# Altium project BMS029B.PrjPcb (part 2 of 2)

## Sheet BMS029B_FETs.SchDoc: FETs
size 431 x 279 mm; Date: Not shown in title block; ApprovedBy: Not shown in title block; CheckedBy: Not shown in title block; Author: Not shown in title block; CompanyName: Not shown in title block; DrawnBy: M Sunna; Engineer: Not shown in title block; Organization: Not shown in title block; Address1: Not shown in title block; Address2: Not shown in title block; Address3: Not shown in title block; Address4: Not shown in title block; DocumentNumber: 3; Revision: Use project parameter SCH_Rev; SheetNumber: 3; SheetTotal: 5; PageSetup: Record=PageOptions¦CenterHorizontal=True¦CenterVertical=True¦PrintScale=1.00¦XCorrection=1.00¦YCorrection=1.00¦PrintKind=0¦BorderSize=5000000¦LeftOffset=0¦BottomOffset=0¦Orientation=2¦PaperLength=1000¦PaperWidth=1000¦Scale=100¦PaperSource=15¦PrintQuality=600¦MediaType=1¦DitherType=10¦PaperKind=Letter¦PrintScaleMode=1
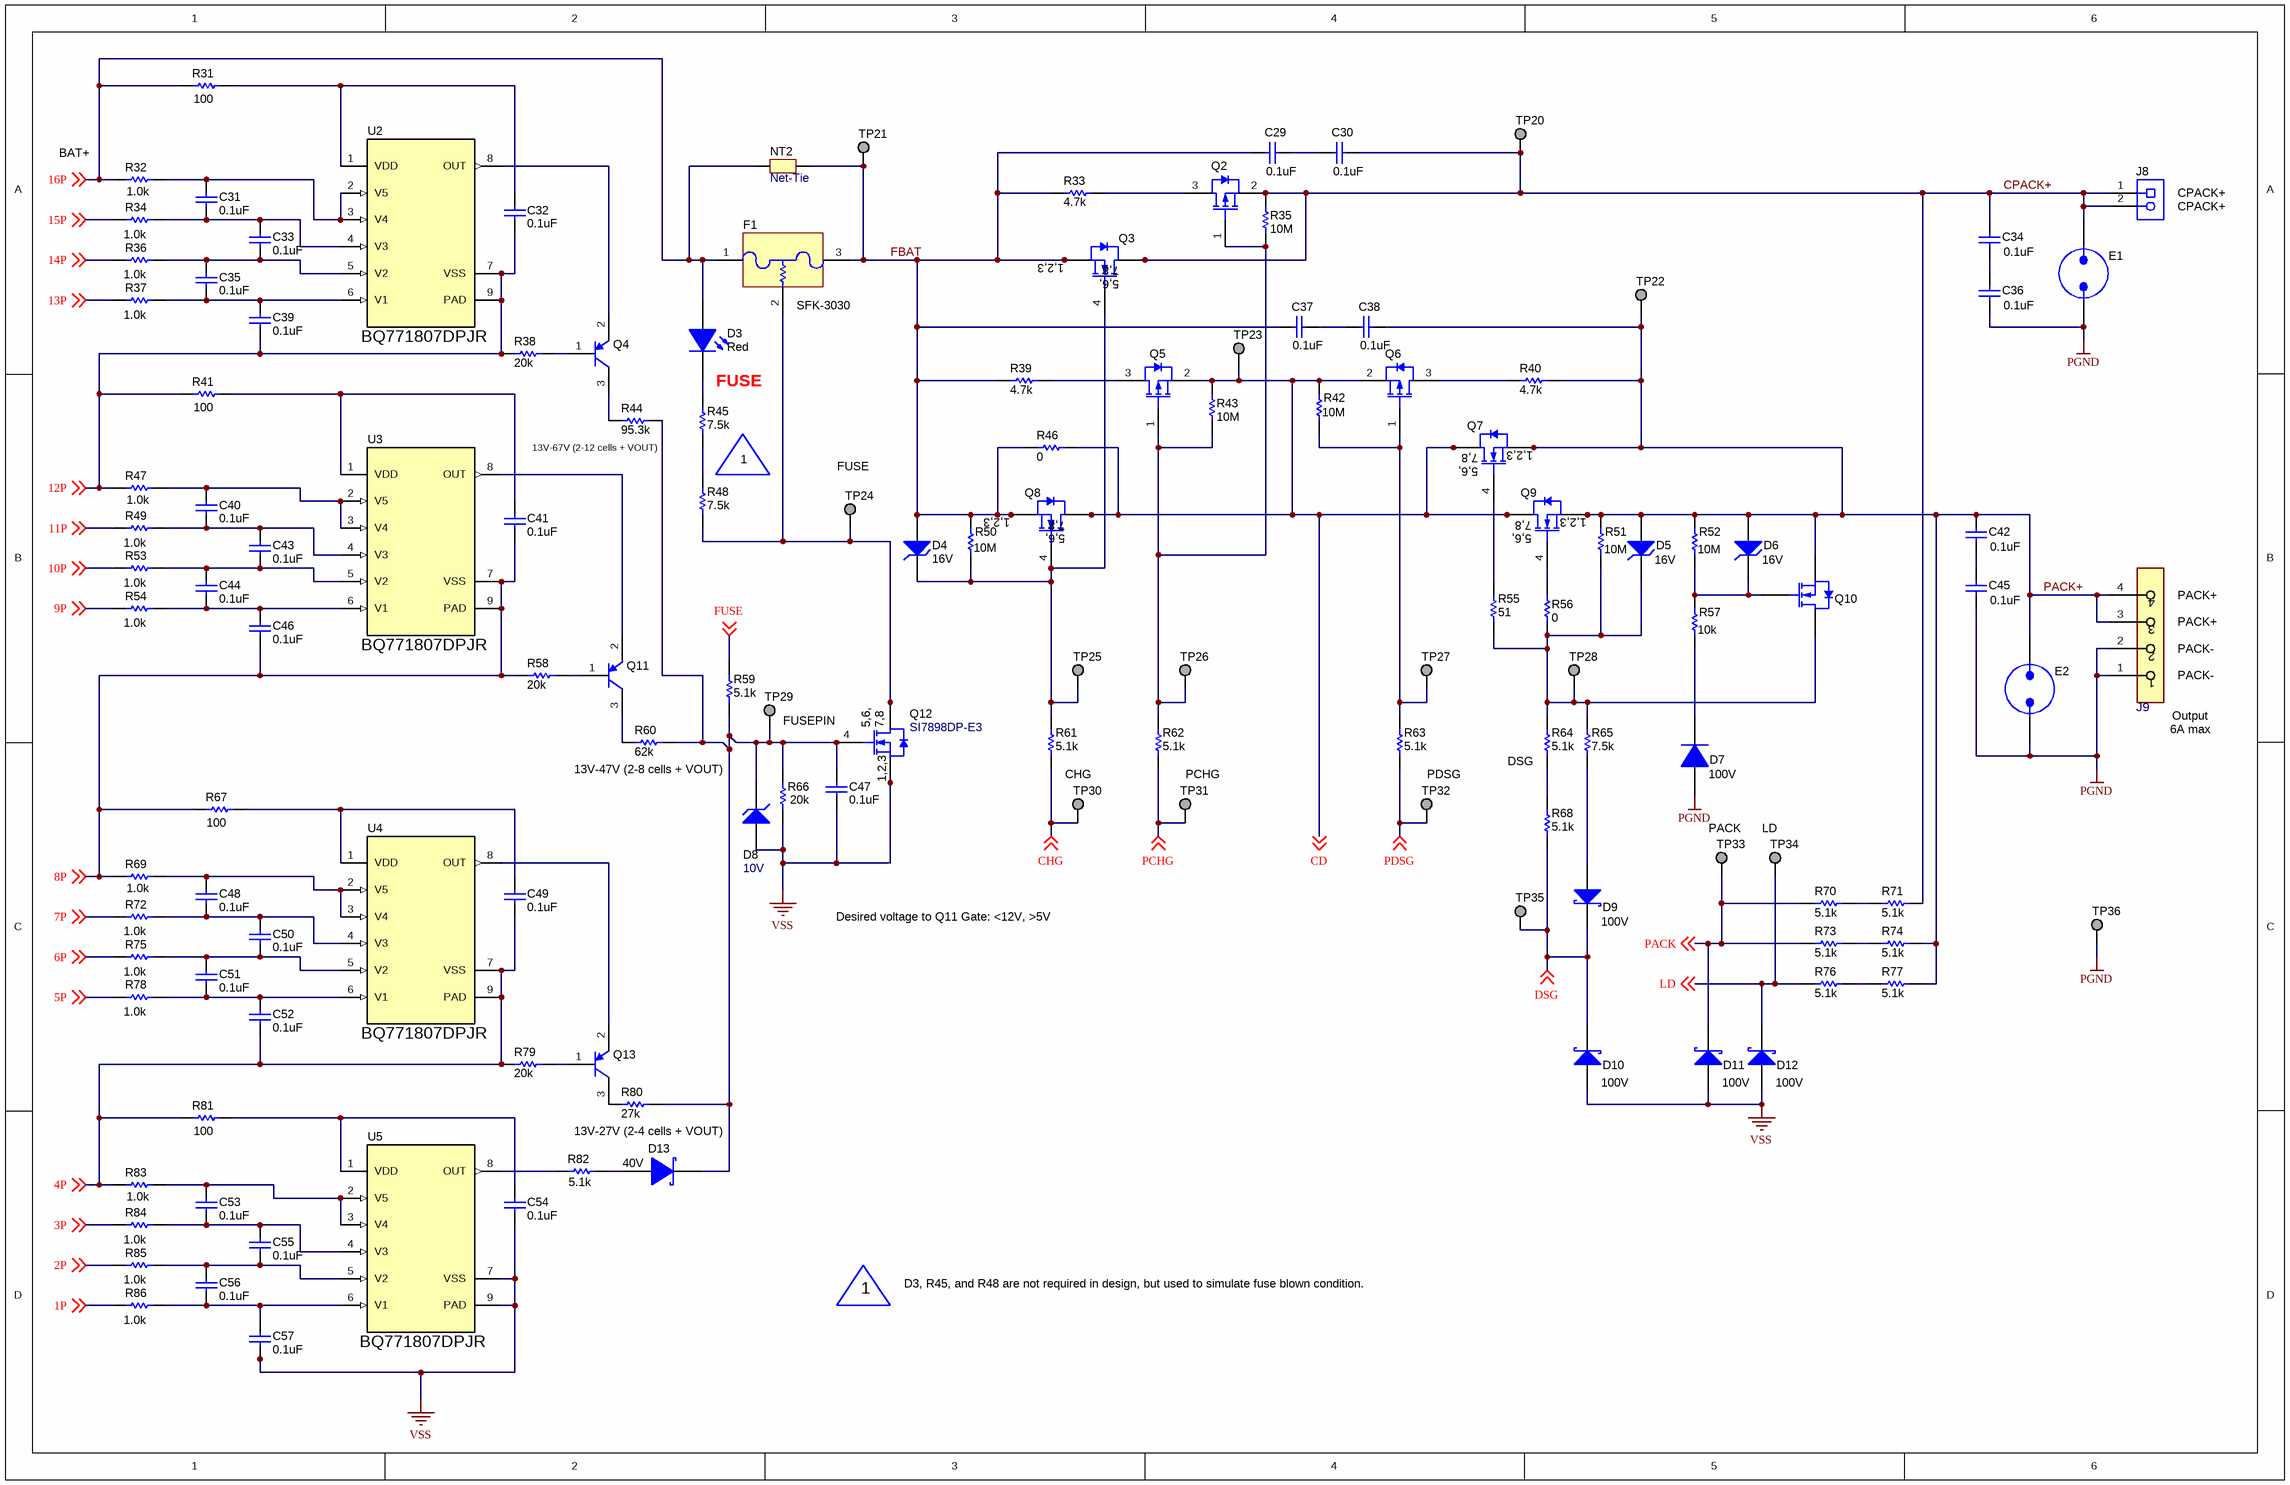
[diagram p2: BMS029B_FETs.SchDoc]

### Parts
C29  ValueDisplayed: 0.1uF  [0603]  (hidden comment: GCJ188R72A104KA01D)
C30  ValueDisplayed: 0.1uF  [0603]  (hidden comment: GCJ188R72A104KA01D)
C31  ValueDisplayed: 0.1uF  [0603]  (hidden comment: 885012206095)
C32  ValueDisplayed: 0.1uF  [0603]  (hidden comment: 885012206095)
C33  ValueDisplayed: 0.1uF  [0603]  (hidden comment: 885012206095)
C34  ValueDisplayed: 0.1uF  [0603]  (hidden comment: GCJ188R72A104KA01D)
C35  ValueDisplayed: 0.1uF  [0603]  (hidden comment: 885012206095)
C36  ValueDisplayed: 0.1uF  [0603]  (hidden comment: GCJ188R72A104KA01D)
C37  ValueDisplayed: 0.1uF  [0603]  (hidden comment: GCJ188R72A104KA01D)
C38  ValueDisplayed: 0.1uF  [0603]  (hidden comment: GCJ188R72A104KA01D)
C39  ValueDisplayed: 0.1uF  [0603]  (hidden comment: 885012206095)
C40  ValueDisplayed: 0.1uF  [0603]  (hidden comment: 885012206095)
C41  ValueDisplayed: 0.1uF  [0603]  (hidden comment: 885012206095)
C42  ValueDisplayed: 0.1uF  [0603]  (hidden comment: GCJ188R72A104KA01D)
C43  ValueDisplayed: 0.1uF  [0603]  (hidden comment: 885012206095)
C44  ValueDisplayed: 0.1uF  [0603]  (hidden comment: 885012206095)
C45  ValueDisplayed: 0.1uF  [0603]  (hidden comment: GCJ188R72A104KA01D)
C46  ValueDisplayed: 0.1uF  [0603]  (hidden comment: 885012206095)
C47  ValueDisplayed: 0.1uF  [0603]  (hidden comment: 885012206095)
C48  ValueDisplayed: 0.1uF  [0603]  (hidden comment: 885012206095)
C49  ValueDisplayed: 0.1uF  [0603]  (hidden comment: 885012206095)
C50  ValueDisplayed: 0.1uF  [0603]  (hidden comment: 885012206095)
C51  ValueDisplayed: 0.1uF  [0603]  (hidden comment: 885012206095)
C52  ValueDisplayed: 0.1uF  [0603]  (hidden comment: 885012206095)
C53  ValueDisplayed: 0.1uF  [0603]  (hidden comment: 885012206095)
C54  ValueDisplayed: 0.1uF  [0603]  (hidden comment: 885012206095)
C55  ValueDisplayed: 0.1uF  [0603]  (hidden comment: 885012206095)
C56  ValueDisplayed: 0.1uF  [0603]  (hidden comment: 885012206095)
C57  ValueDisplayed: 0.1uF  [0603]  (hidden comment: 885012206095)
D3  value Red  [WL-SMCW_RED]  (hidden comment: 150060RS75000)
D4  value 16V  [SOD-123]  (hidden comment: MMSZ5246B-7-F)
D5  value 16V  [SOD-123]  (hidden comment: MMSZ5246B-7-F)
D6  value 16V  [SOD-123]  (hidden comment: MMSZ5246B-7-F)
D7  value 100V  [SOD-123]  (hidden comment: 1N4148W-7-F)
D8  value 10V  [SOD-123]  (hidden comment: MMSZ4697T1G)
D9  value 100V  [SOD-123]  (hidden comment: BAT46W-7-F)
D10  value 100V  [SOD-123]  (hidden comment: BAT46W-7-F)
D11  value 100V  [SOD-123]  (hidden comment: BAT46W-7-F)
D12  value 100V  [SOD-123]  (hidden comment: BAT46W-7-F)
D13  value 40V  [SOT-323]  (hidden comment: BAS40W-7-F)
E1  Spark Gap  [SPARK_GAP2]  (value not drawn)  (no BOM)
E2  Spark Gap  [SPARK_GAP2]  (value not drawn)  (no BOM)
F1  SFK-3030  [FUSE_SFK-xx30x]
J8  ED555/2DS  [TERM_BLK_ED555-2DS]  (value not drawn)
J9  OSTTE040161  [FP-OSTTE040161_HDR4-MFG]  (value not drawn)
NT2  Net-Tie  [Net-Tie_50milWide_30milLong]  (net tie, no BOM)
Q2  SI2325DS-T1-E3  [SOT-23]  (value not drawn)
Q3  BSZ900N15NS3 G  [PG-TSDSON-8]  (value not drawn)
Q4  MMBT5401LT1G  [SOT-23]  (value not drawn)
Q5  SI2325DS-T1-E3  [SOT-23]  (value not drawn)
Q6  SI2325DS-T1-E3  [SOT-23]  (value not drawn)
Q7  BSC160N15NS5ATMA1  [PG-TDSON-8]  (value not drawn)
Q8  BSC160N15NS5ATMA1  [PG-TDSON-8]  (value not drawn)
Q9  BSC160N15NS5ATMA1  [PG-TDSON-8]  (value not drawn)
Q10  MOSFET_N_D3G1S2  [SOT-323]  (value not drawn)
Q11  MMBT5401LT1G  [SOT-23]  (value not drawn)
Q12  SI7898DP-E3  [PowerPAK_SO-8]
Q13  MMBT5401LT1G  [SOT-23]  (value not drawn)
R31  ValueDisplayed: 100  [0603]  (hidden comment: Resistor)
R32  ValueDisplayed: 1.0k  [0603]  (hidden comment: Resistor)
R33  ValueDisplayed: 4.7k  [2512]  (hidden comment: CRCW25124K70JNEG)
R34  ValueDisplayed: 1.0k  [0603]  (hidden comment: Resistor)
R35  ValueDisplayed: 10M  [0603]  (hidden comment: Resistor)
R36  ValueDisplayed: 1.0k  [0603]  (hidden comment: Resistor)
R37  ValueDisplayed: 1.0k  [0603]  (hidden comment: Resistor)
R38  ValueDisplayed: 20k  [0603]  (hidden comment: CRCW060320K0JNEA)
R39  ValueDisplayed: 4.7k  [2512]  (hidden comment: CRCW25124K70JNEG)
R40  ValueDisplayed: 4.7k  [2512]  (hidden comment: CRCW25124K70JNEG)
R41  ValueDisplayed: 100  [0603]  (hidden comment: Resistor)
R42  ValueDisplayed: 10M  [0603]  (hidden comment: Resistor)
R43  ValueDisplayed: 10M  [0603]  (hidden comment: Resistor)
R44  ValueDisplayed: 95.3k  [0603]  (hidden comment: RC0603FR-0795K3L)
R45  ValueDisplayed: 7.5k  [1206]  (hidden comment: CRCW12067K50JNEA)
R46  ValueDisplayed: 0  [2512_WIDE_VISHAY]  (hidden comment: Resistor)
R47  ValueDisplayed: 1.0k  [0603]  (hidden comment: Resistor)
R48  ValueDisplayed: 7.5k  [1206]  (hidden comment: CRCW12067K50JNEA)
R49  ValueDisplayed: 1.0k  [0603]  (hidden comment: Resistor)
R50  ValueDisplayed: 10M  [0603]  (hidden comment: Resistor)
R51  ValueDisplayed: 10M  [0603]  (hidden comment: Resistor)
R52  ValueDisplayed: 10M  [0603]  (hidden comment: Resistor)
R53  ValueDisplayed: 1.0k  [0603]  (hidden comment: Resistor)
R54  ValueDisplayed: 1.0k  [0603]  (hidden comment: Resistor)
R55  ValueDisplayed: 51  [0603]  (hidden comment: CRCW060351R0JNEA)
R56  ValueDisplayed: 0  [0603]  (hidden comment: CRCW06030000Z0EA)
R57  ValueDisplayed: 10k  [0603]  (hidden comment: Resistor)
R58  ValueDisplayed: 20k  [0603]  (hidden comment: CRCW060320K0JNEA)
R59  ValueDisplayed: 5.1k  [0603]  (hidden comment: Resistor)
R60  ValueDisplayed: 62k  [0603]  (hidden comment: RC0603JR-0762KL)
R61  ValueDisplayed: 5.1k  [0603]  (hidden comment: CRCW06035K10JNEA)
R62  ValueDisplayed: 5.1k  [0603]  (hidden comment: CRCW06035K10JNEA)
R63  ValueDisplayed: 5.1k  [0603]  (hidden comment: CRCW06035K10JNEA)
R64  ValueDisplayed: 5.1k  [1206]  (hidden comment: CRCW12065K10JNEA)
R65  ValueDisplayed: 7.5k  [0603]  (hidden comment: CRCW06037K50JNEA)
R66  ValueDisplayed: 20k  [0603]  (hidden comment: Resistor)
R67  ValueDisplayed: 100  [0603]  (hidden comment: Resistor)
R68  ValueDisplayed: 5.1k  [1206]  (hidden comment: CRCW12065K10JNEA)
R69  ValueDisplayed: 1.0k  [0603]  (hidden comment: Resistor)
R70  ValueDisplayed: 5.1k  [1206]  (hidden comment: CRCW12065K10JNEA)
R71  ValueDisplayed: 5.1k  [1206]  (hidden comment: CRCW12065K10JNEA)
R72  ValueDisplayed: 1.0k  [0603]  (hidden comment: Resistor)
R73  ValueDisplayed: 5.1k  [1206]  (hidden comment: CRCW12065K10JNEA)
R74  ValueDisplayed: 5.1k  [1206]  (hidden comment: CRCW12065K10JNEA)
R75  ValueDisplayed: 1.0k  [0603]  (hidden comment: Resistor)
R76  ValueDisplayed: 5.1k  [1206]  (hidden comment: CRCW12065K10JNEA)
R77  ValueDisplayed: 5.1k  [1206]  (hidden comment: CRCW12065K10JNEA)
R78  ValueDisplayed: 1.0k  [0603]  (hidden comment: Resistor)
R79  ValueDisplayed: 20k  [0603]  (hidden comment: CRCW060320K0JNEA)
R80  ValueDisplayed: 27k  [0603]  (hidden comment: CRCW060327K0JNEA)
R81  ValueDisplayed: 100  [0603]  (hidden comment: Resistor)
R82  ValueDisplayed: 5.1k  [0603]  (hidden comment: Resistor)
R83  ValueDisplayed: 1.0k  [0603]  (hidden comment: Resistor)
R84  ValueDisplayed: 1.0k  [0603]  (hidden comment: Resistor)
R85  ValueDisplayed: 1.0k  [0603]  (hidden comment: Resistor)
R86  ValueDisplayed: 1.0k  [0603]  (hidden comment: Resistor)
TP20  TESTPOINT  [TP_VIA_060RND040]  (value not drawn)  (no BOM)
TP21  TESTPOINT  [TP_VIA_060RND040]  (value not drawn)  (no BOM)
TP22  TESTPOINT  [TP_VIA_060RND040]  (value not drawn)  (no BOM)
TP23  TESTPOINT  [TP_VIA_060RND040]  (value not drawn)  (no BOM)
TP24  TESTPOINT  [TP_VIA_060RND040]  (value not drawn)  (no BOM)
TP25  TESTPOINT  [TP_VIA_060RND040]  (value not drawn)  (no BOM)
TP26  TESTPOINT  [TP_VIA_060RND040]  (value not drawn)  (no BOM)
TP27  TESTPOINT  [TP_VIA_060RND040]  (value not drawn)  (no BOM)
TP28  TESTPOINT  [TP_VIA_060RND040]  (value not drawn)  (no BOM)
TP29  TESTPOINT  [TP_VIA_060RND040]  (value not drawn)  (no BOM)
TP30  TESTPOINT  [TP_VIA_060RND040]  (value not drawn)  (no BOM)
TP31  TESTPOINT  [TP_VIA_060RND040]  (value not drawn)  (no BOM)
TP32  TESTPOINT  [TP_VIA_060RND040]  (value not drawn)  (no BOM)
TP33  TESTPOINT  [TP_VIA_060RND040]  (value not drawn)  (no BOM)
TP34  TESTPOINT  [TP_VIA_060RND040]  (value not drawn)  (no BOM)
TP35  TESTPOINT  [TP_VIA_060RND040]  (value not drawn)  (no BOM)
TP36  TESTPOINT  [TP_VIA_060RND040]  (value not drawn)  (no BOM)
U2  BQ771807DPJR  [DPJ0008A]
U3  BQ771807DPJR  [DPJ0008A]
U4  BQ771807DPJR  [DPJ0008A]
U5  BQ771807DPJR  [DPJ0008A]

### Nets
PGND: C36.2 C45.2 D7.2(A) E1.2 E2.2 J9.1 J9.2 TP36.1
VSS: C47.1 C54.1 C57.1 D8.2(A) D10.2(A) D11.2(A) D12.2(A) Q12.1(S) Q12.2(S) Q12.3(S) R66.1 U5.7(VSS) U5.9(PAD)
1P: R86.1 ; off-sheet 1P
2P: R85.1 ; off-sheet 2P
3P: R84.1 ; off-sheet 3P
4P: C49.1 C52.1 R79.1 R81.1 R83.1 U4.7(VSS) U4.9(PAD) ; off-sheet 4P
5P: R78.1 ; off-sheet 5P
6P: R75.1 ; off-sheet 6P
7P: R72.1 ; off-sheet 7P
8P: C41.1 C46.1 R58.1 R67.1 R69.1 U3.7(VSS) U3.9(PAD) ; off-sheet 8P
9P: R54.1 ; off-sheet 9P
10P: R53.1 ; off-sheet 10P
11P: R49.1 ; off-sheet 11P
12P: C32.1 C39.1 R38.1 R41.1 R47.1 U2.7(VSS) U2.9(PAD) ; off-sheet 12P
13P: R37.1 ; off-sheet 13P
14P: R36.1 ; off-sheet 14P
15P: R34.1 ; off-sheet 15P
16P: D3.2(A) F1.1(Fuse) NT2.2 R31.1 R32.1 ; off-sheet 16P
CD: Q5.2(S) Q6.2(S) Q7.5(D) Q7.6(D) Q7.7(D) Q7.8(D) Q7.9(D) Q8.5(D) Q8.6(D) Q8.7(D) Q8.8(D) Q8.9(D) Q9.5(D) Q9.6(D) Q9.7(D) Q9.8(D) Q9.9(D) R42.1 R43.1 R46.2 TP23.1 ; off-sheet CD
CHG: R61.1 TP30.1 ; off-sheet CHG
CPACK+: C30.1 C34.1 E1.1 J8.1 J8.2 Q2.2(S) Q3.5(D) Q3.6(D) Q3.7(D) Q3.8(D) Q3.9(D) R35.1 R71.1 TP20.1
DSG: D9.1(K) D10.1(K) R68.1 TP35.1 ; off-sheet DSG
FBAT: C29.2 C37.2 D4.2(A) F1.3(Fuse) NT2.1 Q3.1(S) Q3.2(S) Q3.3(S) Q8.1(S) Q8.2(S) Q8.3(S) R33.1 R39.1 R46.1 R50.1 TP21.1
FUSE: R59.2 ; off-sheet FUSE
LD: D12.1(K) R76.2 TP34.1 ; off-sheet LD
PACK: D11.1(K) R70.2 R73.2 TP33.1 ; off-sheet PACK
PACK+: C38.1 C42.1 D5.2(A) D6.2(A) E2.1 J9.3 J9.4 Q7.1(S) Q7.2(S) Q7.3(S) Q9.1(S) Q9.2(S) Q9.3(S) Q10.2(S) R40.2 R51.1 R52.1 R74.1 R77.1 TP22.1
PCHG: R62.1 TP31.1 ; off-sheet PCHG
PDSG: R63.1 TP32.1 ; off-sheet PDSG
NetC29_1: C29.1 C30.2
NetC31_1: C31.1 C33.2 R34.2 U2.4(V3)
NetC31_2: C31.2 R32.2 U2.2(V5) U2.3(V4)
NetC32_2: C32.2 R31.2 U2.1(VDD)
NetC33_1: C33.1 C35.2 R36.2 U2.5(V2)
NetC34_2: C34.2 C36.1
NetC35_1: C35.1 C39.2 R37.2 U2.6(V1)
NetC37_1: C37.1 C38.2
NetC40_1: C40.1 C43.2 R49.2 U3.4(V3)
NetC40_2: C40.2 R47.2 U3.2(V5) U3.3(V4)
NetC41_2: C41.2 R41.2 U3.1(VDD)
NetC42_2: C42.2 C45.1
NetC43_1: C43.1 C44.2 R53.2 U3.5(V2)
NetC44_1: C44.1 C46.2 R54.2 U3.6(V1)
NetC47_2: C47.2 D8.1(K) D13.3(K) Q12.4(G) R44.2 R59.1 R60.2 R66.2 R80.2 TP29.1
NetC48_1: C48.1 C50.2 R72.2 U4.4(V3)
NetC48_2: C48.2 R69.2 U4.2(V5) U4.3(V4)
NetC49_2: C49.2 R67.2 U4.1(VDD)
NetC50_1: C50.1 C51.2 R75.2 U4.5(V2)
NetC51_1: C51.1 C52.2 R78.2 U4.6(V1)
NetC53_1: C53.1 C55.2 R84.2 U5.4(V3)
NetC53_2: C53.2 R83.2 U5.2(V5) U5.3(V4)
NetC54_2: C54.2 R81.2 U5.1(VDD)
NetC55_1: C55.1 C56.2 R85.2 U5.5(V2)
NetC56_1: C56.1 C57.2 R86.2 U5.6(V1)
NetD3_1: D3.1(K) R45.2
NetD4_1: D4.1(K) Q3.4(G) Q8.4(G) R50.2 R61.2 TP25.1
NetD5_1: D5.1(K) Q10.3(D) R51.2 R55.2 R56.2 R64.2 R65.2 TP28.1
NetD6_1: D6.1(K) Q10.1(G) R52.2 R57.1
NetD7_1: D7.1(K) R57.2
NetD9_2: D9.2(A) R65.1
NetD13_1: D13.1(A) R82.2
NetF1_2: F1.2(Heater) Q12.5(D) Q12.6(D) Q12.7(D) Q12.8(D) Q12.9(D) R48.1 TP24.1
NetQ2_1: Q2.1(G) Q5.1(G) R35.2 R43.2 R62.2 TP26.1
NetQ2_3: Q2.3(D) R33.2
NetQ4_1: Q4.1(B) R38.2
NetQ4_2: Q4.2(E) U2.8(OUT)
NetQ4_3: Q4.3(C) R44.1
NetQ5_3: Q5.3(D) R39.2
NetQ6_1: Q6.1(G) R42.2 R63.2 TP27.1
NetQ6_3: Q6.3(D) R40.1
NetQ7_4: Q7.4(G) R55.1
NetQ9_4: Q9.4(G) R56.1
NetQ11_1: Q11.1(B) R58.2
NetQ11_2: Q11.2(E) U3.8(OUT)
NetQ11_3: Q11.3(C) R60.1
NetQ13_1: Q13.1(B) R79.2
NetQ13_2: Q13.2(E) U4.8(OUT)
NetQ13_3: Q13.3(C) R80.1
NetR45_1: R45.1 R48.2
NetR64_1: R64.1 R68.2
NetR70_1: R70.1 R71.2
NetR73_1: R73.1 R74.2
NetR76_1: R76.1 R77.2
NetR82_1: R82.1 U5.8(OUT)

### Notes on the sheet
- BAT+
- (near J8) CPACK+
- FUSE
- (near R44) 13V-67V (2-12 cells + VOUT)
- 1
- (near TP24) FUSE
- (near J9) PACK+
- (near J9) PACK-
- (near R60) 13V-47V (2-8 cells + VOUT)
- (near TP29) FUSEPIN
- (near R64) DSG
- (near J9) Output
- 6A max
- CHG
- PCHG
- PDSG
- (near TP33) PACK
- (near TP34) LD
- Desired voltage to Q11 Gate: <12V, >5V
- 13V-27V (2-4 cells + VOUT)
- D3, R45, and R48 are not required in design, but used to simulate fuse blown condition.

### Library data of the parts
C29 C30 C34 C36-C38 C42 C45 = CMP-0064935-4: CAP, CERM, 0.1 uF, 100 V,+/- 10%, X7R, AEC-Q200 Grade 1, 0603; Manufacturer: MuRata; TaMin_C: -55°C; Polarized: N; SizeAreaWB_mm2: 4.68; Value1: Unknown; U/M: EA; Value: 0.1uF; TaMax_C: 125°C; SizeZ_mm: 1; SizeX_mm: 1.6; SizeY_mm: 0.8; Value2: 100V; SizeArea_mm2: 1.28; AEC Qualified: Y; Cap_F: 100nF; AEC Category: Q200
C31-C33 C35 C39-C41 C43 C44 C46-C57 = CMP-0006837-4: CAP, CERM, 0.1 uF, 50 V, +/- 10%, X7R, 0603; Manufacturer: Wurth Elektronik; Polarized: N; Value: 0.1uF; U/M: EA; Cap_F: 100nF; Value1: Unknown; VDC_V: 50V; TaMin_C: -55°C; TaMax_C: 125°C; SizeArea_mm2: 1.28; SizeAreaWB_mm2: 4.68; SizeX_mm: 1.6; SizeY_mm: 0.8; SizeZ_mm: 1; AEC Category: Q200
D3 = CMP-0002947-3: LED, Red, SMD; Manufacturer: Wurth Elektronik; Type: AlInGaP; Vf_V: 2V; Io_A: 30mA; Vr_V: 5V; Tjmax_C: 85°C; Power_TotalModule: 72mW; Value1: 0.072W; Angle: 140
D4 = CMP-0005754-4: Diode, Zener, 16 V, 500 mW, SOD-123; Manufacturer: Diodes Inc.; Power_W: 500mW; SizeAreaWB_mm2: 13.095; Value1: 0.5W; RJA_CperW: 350; SizeZ_mm: 1.35; SizeX_mm: 3.85; SizeY_mm: 1.7; SizeArea_mm2: 6.545; AEC Category: Q101
D5 D6 = CMP-0005754-4: Diode, Zener, 16 V, 500 mW, SOD-123; Manufacturer: Diodes Inc.; Power_W: 500mW; SizeY_mm: 1.7; Value1: 0.5W; SizeX_mm: 3.85; RJA_CperW: 350; SizeAreaWB_mm2: 13.095; SizeArea_mm2: 6.545; AEC Category: Q101; SizeZ_mm: 1.35
D7 = CMP-0029001-2: Diode, Ultrafast, 100 V, 0.15 A, SOD-123; Manufacturer: Diodes Inc.; Vf_V: 1.25V; Value1: 0.15A; Io_A: 1.5dA; TJmax_C: 150°C; SizeAreaWB_mm2: 13.095; SizeArea_mm2: 6.545; SizeX_mm: 3.85; SizeY_mm: 1.7; SizeZ_mm: 1.35; AEC Category: Q101; Green_Lifecycle: Active; Green_REACh: Passed
D8 = CMP-0005740-3: Diode, Zener, 10 V, 500 mW, SOD-123; Manufacturer: ON Semiconductor; SizeY_mm: 1.7; SizeX_mm: 3.85; RJA_CperW: 340; SizeAreaWB_mm2: 13.095; AEC Category: Q101; Power_W: 500mW; SizeZ_mm: 1.35; Value1: 0.5W; SizeArea_mm2: 6.545
D9-D12 = CMP-0028450-2: Diode, Schottky, 100 V, 0.15 A, SOD-123; Manufacturer: Diodes Inc.; Io_A: 150mA; SizeArea_mm2: 6.545; SizeX_mm: 3.85; Value2: 0.6V; Value1: 0.15A; AEC Category: Q101; SizeZ_mm: 1.35; SizeY_mm: 1.7; Green_Lifecycle: Active; Green_REACh: Passed; SizeAreaWB_mm2: 13.095; Vf_V: 600mV
D13 = CMP-0028438-2: Diode, Schottky, 40 V, 0.2 A, SOT-323; Manufacturer: Diodes Inc.; Value2: 0.9V; SizeArea_mm2: 4.84; Vf_V: 9dV; Value1: 0.2A; Green_Lifecycle: Not Set; SizeAreaWB_mm2: 10.24; SizeX_mm: 2.2; AEC Category: Q101; Io_A: 2dA; Green_REACh: Incomplete; SizeZ_mm: 1.1
E1 E2 = CMP-0079939-1
F1 = CMP-0078325-2: Fuse, 30 A, 62 VDC, SMD; Manufacturer: Dexerials Corporation; Irating_A: 30A; VDC_V: 62V; Rtyp_Ohm: 1.75m
J8 = CMP-0074913-1: Terminal Block, 3.5mm Pitch, 2x1, TH; Manufacturer: On-Shore Technology; Cert_VDE: Y; CNHeader: False; Current_A: 6A; Green_Lifecycle: Active; Shrouded: N; Gender: Female; Green_REACh: Passed; Voltage_V: 150V; Row_Count: 1; Pitch_mm: 3.5; ContactFinish: Brass; CT: True
J9 = CMP-0087048-1: TERM BLOCK 3.5MM VERT 4POS PCB; Manufacturer: On Shore Technology; Row_Count: 1; Current_A: 10A; ContactFinish: Tin; Voltage_V: 300V
NT2 = CMP-0078142-3: Single point connection between nets.
Q2 Q5 Q6 = CMP-0000093-3: MOSFET, P-CH, -150 V, -0.53 A, SOT-23; Manufacturer: Vishay-Siliconix; Alternate Manufacturer: None; SizeZ_mm: 1.1; SizeAreaWB_mm2: 14; Value: -150V; SizeY_mm: 3; AEC Category: Q101; IdsMax_A: -530mA; Value2: 7.7 nC; ChMode: Enhancement; QgTyp_nC: 7.7; Vgs_V: -20V; ChType: P; SizeX_mm: 2.5; SizeArea_mm2: 7.5; AEC Qualified: N
Q3 = CMP-0001051-2: MOSFET, N-CH, 150 V, 13 A, PG-TSDSON-8; Alternate Manufacturer: None; Manufacturer: Infineon Technologies; SizeZ_mm: 1.1; ChType: N; Value2: 5 nC; VdsMax_V: 150V; SizeX_mm: 3.4; Vgs_V: 20V; QgTyp_nC: 5; Value: 150V; SizeArea_mm2: 11.56; AEC Category: Q101; IdsMax_A: 13A; SizeAreaWB_mm2: 19.36; U/M: EA
Q4 Q11 Q13 = CMP-0000333-2: Transistor, PNP, 150 V, 0.5 A, SOT-23; Manufacturer: ON Semiconductor; TaMax_C: 150°C; Value2: 240; Value1: 0.5 A; Vcesat1_V: 500mV; SizeX_mm: 2.5; SizeY_mm: 3; TaMin_C: -55°C; IcRated_A: 500mA; CompType: BJT; SizeZ_mm: 1.1; Value: 150 V; SizeArea_mm2: 7.5; NPN: 0; Vceo_V: 150V; PNP: 1; AEC Category: Q101; SizeAreaWB_mm2: 14; U/M: EA
Q7-Q9 = CMP-0067566-1: MOSFET, N-CH, 150 V, 56 A, PG-TDSON-8; Alternate Manufacturer: None; Manufacturer: Infineon Technologies; QgTyp_nC: 19.0; SizeAreaWB_mm2: 55.131; Vgs_V: 20V; Value1: ? ohm; VdsMax_V: 150V; U/M: EA; Value: 150V; IdsMax_A: 56A; SizeZ_mm: 1.12; SizeX_mm: 5.99; SizeY_mm: 4.9; Value2: 19 nC; SizeArea_mm2: 29.351; ChType: N; AEC Category: Q101
Q10 = CMP-0000774-1: MOSFET, N-CH, 60 V, 0.31 A, SOT-323; PartNumber: 2N7002KW; Manufacturer: Fairchild Semiconductor; Alternate Manufacturer: None; Value: 60V; U/M: EA; ChType: N; Value1: 1; Rdson45_ohm: 1.6; Vgs_V: 2.1V; IdsMax_A: 3.1dA; SizeAreaWB_mm2: 10.24; SizeArea_mm2: 4.84; SizeX_mm: 2.2; SizeZ_mm: 1.1; AEC Category: Q101; Green_Lifecycle: Active; Green_REACh: Passed
Q12 = CMP-0001069-3: MOSFET, N-CH, 150 V, 3 A, PowerPAK SO-8; Alternate Manufacturer: None; Manufacturer: Vishay-Siliconix; SizeZ_mm: 1.12; ChType: N; Value2: 17 nC; Value1: 0.07; VdsMax_V: 150V; SizeX_mm: 5.99; SizeAreaWB_mm2: 55.131; SizeY_mm: 4.9; Vgs_V: 20V; QgTyp_nC: 17; Value: 150V; Rdson45_ohm: 0.076; SizeArea_mm2: 29.351; AEC Category: Q101; IdsMax_A: 3A; U/M: EA
R31 R41 R67 R81 = CMP-0025700-4: RES, 100, 5%, 0.1 W, AEC-Q200 Grade 0, 0603; PartNumber: CRCW0603100RJNEA; Manufacturer: Vishay-Dale; Value: 100; Value_Code: 100R; Power_W: 100mW; Value2: 0.1W; VDC_V: 75V; TempCo: 200 ppm/C; EIA_Code: E24; U/M: EA; SizeArea_mm2: 1.28; SizeX_mm: 1.6; SizeY_mm: 0.8; SizeZ_mm: 1; AEC Category: Q200; AEC Qualified: Y; AEC Grade: 0
R32 R34 R36 R37 R47 R49 R53 R54 R69 R72 R75 R78 R83-R86 = CMP-0025729-4: RES, 1.0 k, 5%, 0.1 W, AEC-Q200 Grade 0, 0603; PartNumber: CRCW06031K00JNEA; Manufacturer: Vishay-Dale; Value: 1.0k; Res_ohm: 1k; Value_Code: 1k00; Power_W: 100mW; Value2: 0.1W; VDC_V: 75V; TempCo: 200 ppm/C; EIA_Code: E24; U/M: EA; SizeArea_mm2: 1.28; SizeX_mm: 1.6; SizeY_mm: 0.8; SizeZ_mm: 1; AEC Category: Q200; AEC Qualified: Y; AEC Grade: 0
R33 R39 R40 = CMP-0015972-3: RES, 4.7 k, 5%, 1 W, AEC-Q200 Grade 0, 2512; Manufacturer: Vishay-Dale; Power_W: 1W; TempCo: 200 ppm/C; Value_Code: 4k70; Value: 4.7k; EIA_Code: E24; SizeX_mm: 6.3; SizeY_mm: 3.2; SizeZ_mm: 0.71; SizeArea_mm2: 20.16; AEC Qualified: Y; VDC_V: 500V; AEC Grade: 0; AEC Category: Q200
R35 R42 R43 R50-R52 = CMP-0025702-4: RES, 10 M, 5%, 0.1 W, AEC-Q200 Grade 0, 0603; PartNumber: CRCW060310M0JNEA; Manufacturer: Vishay-Dale; Value: 10Meg; Value_Code: 10M0; Power_W: 100mW; Value2: 0.1W; VDC_V: 75V; TempCo: 200 ppm/C; EIA_Code: E24; U/M: EA; SizeArea_mm2: 1.28; SizeX_mm: 1.6; SizeY_mm: 0.8; SizeZ_mm: 1; AEC Category: Q200; AEC Qualified: Y; AEC Grade: 0
R38 R58 R79 = CMP-0025753-4: RES, 20 k, 5%, 0.1 W, AEC-Q200 Grade 0, 0603; Manufacturer: Vishay-Dale; Value: 20k; Value_Code: 20k0; Power_W: 100mW; Value2: 0.1W; VDC_V: 75V; TempCo: 200 ppm/C; EIA_Code: E24; SizeArea_mm2: 1.28; SizeX_mm: 1.6; SizeY_mm: 0.8; SizeZ_mm: 1; AEC Category: Q200; AEC Qualified: Y; AEC Grade: 0
R44 = CMP-0023326-5: RES, 95.3 k, 1%, 0.1 W, 0603; Manufacturer: Yageo; Power_W: 100mW; TempCo: 100 ppm/C; Value_Code: 95k3; Value: 95.3k; EIA_Code: E96; SizeX_mm: 1.6; SizeY_mm: 0.8; SizeZ_mm: 1; Value2: 0.1W; SizeArea_mm2: 1.28; AEC Qualified: N; VDC_V: 75V; AEC Category: Q200; SizeAreaWB_mm2: 4.68
R45 R48 = CMP-0018728-3: RES, 7.5 k, 5%, 0.25 W, AEC-Q200 Grade 0, 1206; Manufacturer: Vishay-Dale; Power_W: 250mW; TempCo: 200 ppm/C; Value_Code: 7k50; Value: 7.5k; EIA_Code: E24; SizeX_mm: 3.2; SizeY_mm: 1.6; SizeZ_mm: 1.35; Value2: 0.25W; SizeArea_mm2: 5.12; AEC Qualified: Y; VDC_V: 200V; AEC Category: Q200; AEC Grade: 0
R46 = CMP-0015368-2: RES, 0, 5%, 2 W, 2512 WIDE; PartNumber: RCL12250000Z0EG; Manufacturer: Vishay Draloric; Value: 0; Value_Code: 0000; Power_W: 2W; TempCo: ppm/C; EIA_Code: E24; U/M: EA; AEC Category: Q200; Green_Lifecycle: Active; Green_REACh: Passed
R55 = CMP-0025825-4: RES, 51, 5%, 0.1 W, AEC-Q200 Grade 0, 0603; Manufacturer: Vishay-Dale; Value: 51; Value_Code: 51R0; Power_W: 100mW; Value2: 0.1W; VDC_V: 75V; TempCo: 200 ppm/C; EIA_Code: E24; SizeArea_mm2: 1.28; SizeX_mm: 1.6; SizeY_mm: 0.8; SizeZ_mm: 1; AEC Category: Q200; AEC Qualified: Y; AEC Grade: 0
R56 = CMP-0025697-4: RES, 0, 5%, 0.1 W, AEC-Q200 Grade 0, 0603; Manufacturer: Vishay-Dale; Value: 0; Value_Code: 0000; Power_W: 100mW; Value2: 0.1W; VDC_V: 75V; TempCo: 200 ppm/C; EIA_Code: E24; SizeArea_mm2: 1.28; SizeX_mm: 1.6; SizeY_mm: 0.8; SizeZ_mm: 1; AEC Category: Q200; AEC Qualified: Y
R57 = CMP-0025701-4: RES, 10 k, 5%, 0.1 W, AEC-Q200 Grade 0, 0603; PartNumber: CRCW060310K0JNEA; Manufacturer: Vishay-Dale; Value: 10k; Value_Code: 10k0; Power_W: 100mW; Value2: 0.1W; VDC_V: 75V; TempCo: 200 ppm/C; EIA_Code: E24; U/M: EA; SizeArea_mm2: 1.28; SizeX_mm: 1.6; SizeY_mm: 0.8; SizeZ_mm: 1; AEC Category: Q200; AEC Qualified: Y; AEC Grade: 0
R59 R82 = CMP-0025830-4: RES, 5.1 k, 5%, 0.1 W, AEC-Q200 Grade 0, 0603; PartNumber: CRCW06035K10JNEA; Manufacturer: Vishay-Dale; Value: 5.1k; Value_Code: 5k10; Power_W: 100mW; Value2: 0.1W; VDC_V: 75V; TempCo: 200 ppm/C; EIA_Code: E24; U/M: EA; SizeArea_mm2: 1.28; SizeX_mm: 1.6; SizeY_mm: 0.8; SizeZ_mm: 1; AEC Category: Q200; AEC Qualified: Y; AEC Grade: 0
R60 = CMP-0025935-5: RES, 62 k, 5%, 0.1 W, 0603; Manufacturer: Yageo; Power_W: 100mW; TempCo: 100 ppm/C; Value_Code: 62k0; Value: 62k; EIA_Code: E24; SizeX_mm: 1.6; SizeY_mm: 0.8; SizeZ_mm: 1; Value2: 0.1W; SizeArea_mm2: 1.28; AEC Qualified: N; VDC_V: 75V; AEC Category: Q200; SizeAreaWB_mm2: 4.68
R61-R63 = CMP-0025830-4: RES, 5.1 k, 5%, 0.1 W, AEC-Q200 Grade 0, 0603; Manufacturer: Vishay-Dale; Value: 5.1k; Value_Code: 5k10; Power_W: 100mW; Value2: 0.1W; VDC_V: 75V; TempCo: 200 ppm/C; SizeArea_mm2: 1.28; SizeX_mm: 1.6; SizeY_mm: 0.8; SizeZ_mm: 1; EIA_Code: E24; AEC Category: Q200; AEC Qualified: Y; AEC Grade: 0
R64 R68 R70 R71 R73 R74 R76 R77 = CMP-0018703-3: RES, 5.1 k, 5%, 0.25 W, AEC-Q200 Grade 0, 1206; Manufacturer: Vishay-Dale; Value: 5.1k; Value_Code: 5k10; Power_W: 250mW; Value2: 0.25W; VDC_V: 200V; TempCo: 200 ppm/C; SizeArea_mm2: 5.12; SizeX_mm: 3.2; SizeY_mm: 1.6; SizeZ_mm: 1.35; EIA_Code: E24; AEC Category: Q200; AEC Qualified: Y; AEC Grade: 0
R65 = CMP-0025855-4: RES, 7.5 k, 5%, 0.1 W, AEC-Q200 Grade 0, 0603; Manufacturer: Vishay-Dale; Power_W: 100mW; TempCo: 200 ppm/C; Value_Code: 7k50; Value: 7.5k; EIA_Code: E24; SizeX_mm: 1.6; SizeY_mm: 0.8; SizeZ_mm: 1; Value2: 0.1W; SizeArea_mm2: 1.28; AEC Qualified: Y; VDC_V: 75V; AEC Category: Q200; AEC Grade: 0
R66 = CMP-0025753-4: RES, 20 k, 5%, 0.1 W, AEC-Q200 Grade 0, 0603; PartNumber: CRCW060320K0JNEA; Manufacturer: Vishay-Dale; Value: 20k; Value_Code: 20k0; Power_W: 100mW; Value2: 0.1W; VDC_V: 75V; TempCo: 200 ppm/C; EIA_Code: E24; U/M: EA; SizeArea_mm2: 1.28; SizeX_mm: 1.6; SizeY_mm: 0.8; SizeZ_mm: 1; AEC Category: Q200; AEC Qualified: Y; AEC Grade: 0
R80 = CMP-0025766-4: RES, 27 k, 5%, 0.1 W, AEC-Q200 Grade 0, 0603; Manufacturer: Vishay-Dale; Power_W: 100mW; TempCo: 200 ppm/C; Value_Code: 27k0; Value: 27k; EIA_Code: E24; SizeX_mm: 1.6; SizeY_mm: 0.8; SizeZ_mm: 1; Value2: 0.1W; SizeArea_mm2: 1.28; AEC Qualified: Y; VDC_V: 75V; AEC Category: Q200; AEC Grade: 0
TP20-TP36 = CMP-0078143-2: TEST POINT.  No entry in BOM.
U2-U5 = CMP-0078902-2: Family 2-5S Overvoltage Protector with Internal Delay Timer, DPJ0008A (WSON-8); Alternate PartNumber: BQ771807DPJT; Alternate Manufacturer: Texas Instruments; SizeAreaWB_mm2: 20; SizeZ_mm: 0.8; SizeX_mm: 4; SizeY_mm: 3; SizeArea_mm2: 12; CompType: IC; AEC Qualified: N; AEC Category: Q200

## Sheet BMS029B_Interface.SchDoc: Interface
size 431 x 279 mm; Date: Not shown in title block; ApprovedBy: Not shown in title block; CheckedBy: Not shown in title block; Author: Not shown in title block; CompanyName: Not shown in title block; DrawnBy: M Sunna; Engineer: Not shown in title block; Organization: Not shown in title block; Address1: Not shown in title block; Address2: Not shown in title block; Address3: Not shown in title block; Address4: Not shown in title block; DocumentNumber: 4; Revision: Use project parameter SCH_Rev; SheetNumber: 4; SheetTotal: 5; PageSetup: Record=PageOptions¦CenterHorizontal=True¦CenterVertical=True¦PrintScale=1.00¦XCorrection=1.00¦YCorrection=1.00¦PrintKind=0¦BorderSize=5000000¦LeftOffset=0¦BottomOffset=0¦Orientation=2¦PaperLength=1000¦PaperWidth=1000¦Scale=100¦PaperSource=15¦PrintQuality=600¦MediaType=1¦DitherType=10¦PaperKind=Letter¦PrintScaleMode=1
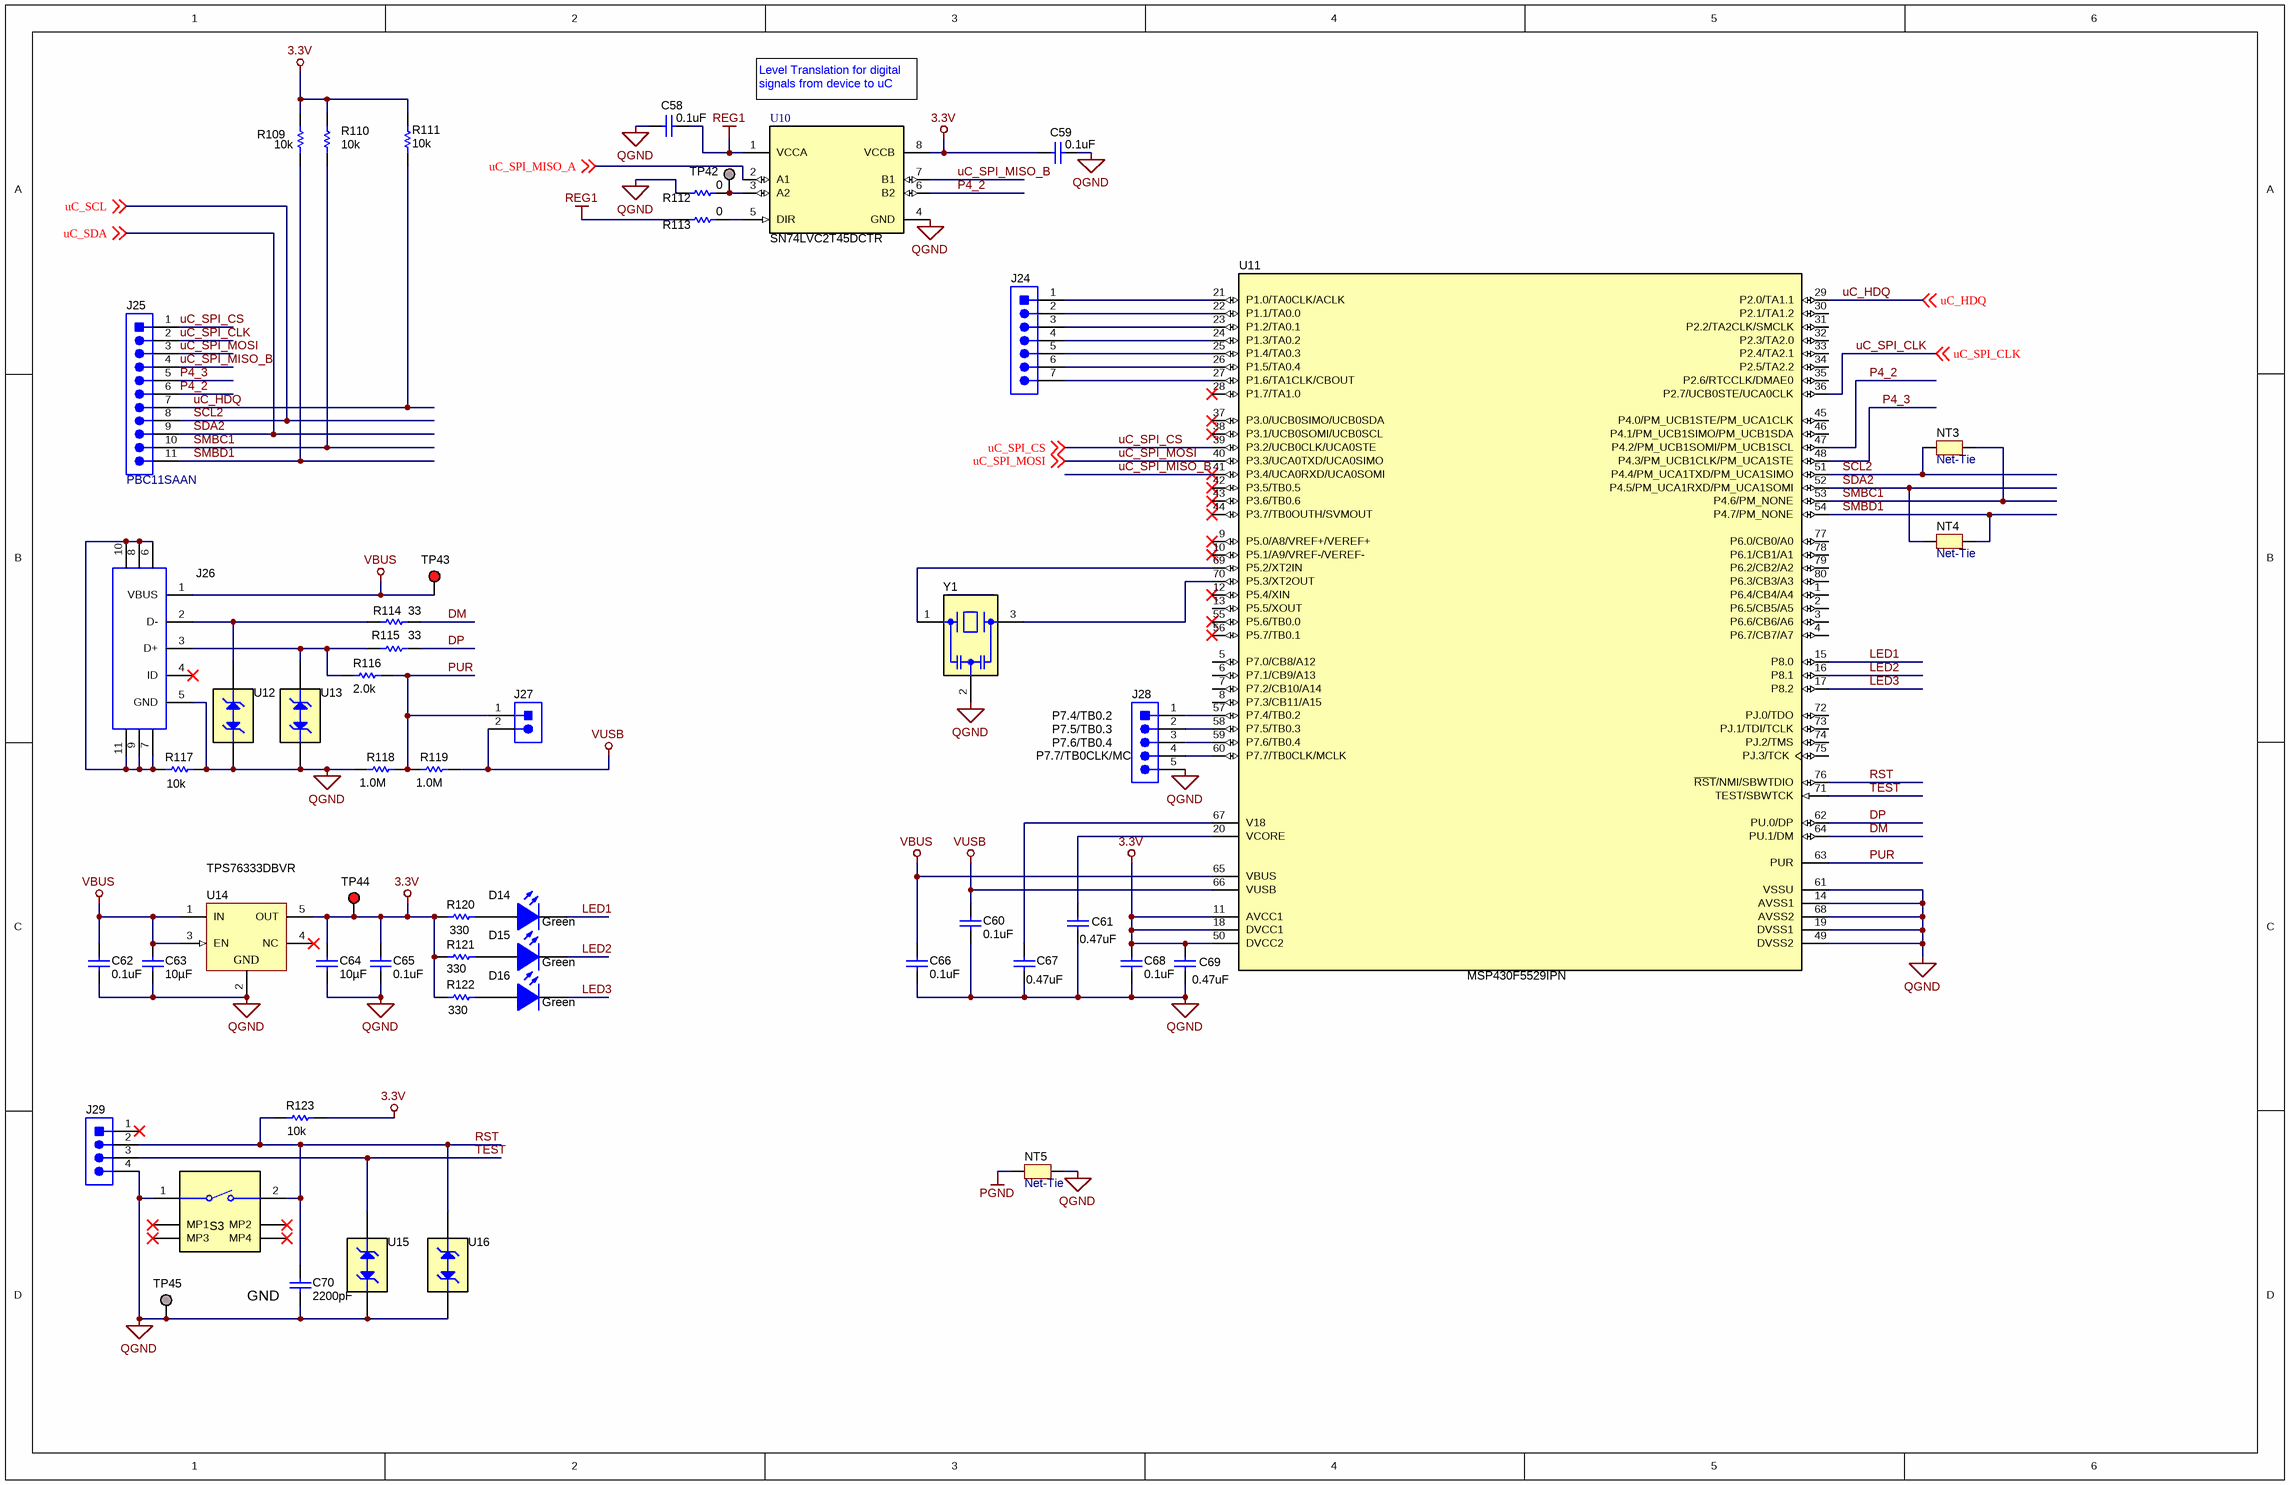
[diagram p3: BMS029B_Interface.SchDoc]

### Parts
C58  ValueDisplayed: 0.1uF  [0402]  (hidden comment: 885012205037)
C59  ValueDisplayed: 0.1uF  [0402]  (hidden comment: 885012205037)
C60  ValueDisplayed: 0.1uF  [0402]  (hidden comment: 885012205037)
C61  ValueDisplayed: 0.47uF  [0402]  (hidden comment: Capacitor)
C62  ValueDisplayed: 0.1uF  [0402]  (hidden comment: 885012205037)
C63  ValueDisplayed: 10µF  [0805_HV]  (hidden comment: CL21A106KOQNNNG)
C64  ValueDisplayed: 10µF  [0805_HV]  (hidden comment: CL21A106KOQNNNG)
C65  ValueDisplayed: 0.1uF  [0402]  (hidden comment: 885012205037)
C66  ValueDisplayed: 0.1uF  [0402]  (hidden comment: 885012205037)
C67  ValueDisplayed: 0.47uF  [0402]  (hidden comment: Capacitor)
C68  ValueDisplayed: 0.1uF  [0402]  (hidden comment: 885012205037)
C69  ValueDisplayed: 0.47uF  [0402]  (hidden comment: Capacitor)
C70  ValueDisplayed: 2200pF  [0402]  (hidden comment: 885012205008)
D14  value Green  [WL-SMCW_GREEN]  (hidden comment: 150060VS75000)
D15  value Green  [WL-SMCW_GREEN]  (hidden comment: 150060VS75000)
D16  value Green  [WL-SMCW_GREEN]  (hidden comment: 150060VS75000)
J24  PBC07SAAN  [Sullins_xxC07SAAN]  (value not drawn)
J25  PBC11SAAN  [Sullins_xxC11SAAN]
J26  CONN_USB_5Pos-6Shld  [Molex_47346-1001]  (value not drawn)
J27  61300211121  [WURTH_61300211121]  (value not drawn)
J28  PEC05SAAN  [Sullins_PxC05SAAN]  (value not drawn)
J29  22284043  [Molex_0022284043]  (value not drawn)
NT3  Net-Tie  [Net-Tie_10mil]  (net tie, no BOM)
NT4  Net-Tie  [Net-Tie_10mil]  (net tie, no BOM)
NT5  Net-Tie  [Net-Tie_0805_HV_NoOverlay]  (net tie, no BOM)
R109  ValueDisplayed: 10k  [0603]  (hidden comment: CRCW060310K0JNEA)
R110  ValueDisplayed: 10k  [0603]  (hidden comment: CRCW060310K0JNEA)
R111  ValueDisplayed: 10k  [0603]  (hidden comment: CRCW060310K0JNEA)
R112  ValueDisplayed: 0  [0603]  (hidden comment: CRCW06030000Z0EA)
R113  ValueDisplayed: 0  [0603]  (hidden comment: CRCW06030000Z0EA)
R114  ValueDisplayed: 33  [0402]  (hidden comment: Resistor)
R115  ValueDisplayed: 33  [0402]  (hidden comment: Resistor)
R116  ValueDisplayed: 2.0k  [0402]  (hidden comment: Resistor)
R117  ValueDisplayed: 10k  [0402]  (hidden comment: Resistor)
R118  ValueDisplayed: 1.0M  [0402]  (hidden comment: Resistor)
R119  ValueDisplayed: 1.0M  [0402]  (hidden comment: Resistor)
R120  ValueDisplayed: 330  [0402]  (hidden comment: Resistor)
R121  ValueDisplayed: 330  [0402]  (hidden comment: Resistor)
R122  ValueDisplayed: 330  [0402]  (hidden comment: Resistor)
R123  ValueDisplayed: 10k  [0402]  (hidden comment: Resistor)
S3  PTS820 J20M SMTR LFS  [SW_PTS820]  (value not drawn)
TP42  TESTPOINT  [TP_50MIL-25MILHOLE]  (value not drawn)  (no BOM)
TP43  5005  [Keystone5005]  (value not drawn)
TP44  5005  [Keystone5005]  (value not drawn)
TP45  TESTPOINT  [TP_SM_1MM]  (value not drawn)  (no BOM)
U10  SN74LVC2T45DCTR  [DCT0008A_N]
U11  PartNumber: MSP430F5529IPN  [PN0080A_N]  (hidden comment: CMP-0038965-1)
U12  TPD1E10B06DPYT  [DPY0002A]  (value not drawn)
U13  TPD1E10B06DPYT  [DPY0002A]  (value not drawn)
U14  PartNumber: TPS76333DBVR  [DBV0005A_N]  (hidden comment: CMP-0035539-1)
U15  TPD1E10B06DPYT  [DPY0002A]  (value not drawn)
U16  TPD1E10B06DPYT  [DPY0002A]  (value not drawn)
Y1  CSTCR4M00G55B-R0  [Murata_CSTCR_G]  (value not drawn)

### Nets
3.3V: C59.2 C64.1 C65.1 C68.1 C69.1 R109.1 R110.1 R111.1 R120.2 R121.2 R122.2 R123.2 TP44.1 U10.8(VCCB) U11.11(AVCC1) U11.18(DVCC1) U11.50(DVCC2) U14.5(OUT)
PGND: NT5.2
QGND: C58.1 C59.1 C60.2 C61.2 C62.2 C63.2 C64.2 C65.2 C66.2 C67.2 C68.2 C69.2 C70.2 J26.5(GND) J28.5 J29.4 NT5.1 R112.1 R117.1 R118.1 S3.1 TP45.1 U10.4(GND) U11.14(AVSS1) U11.19(DVSS1) U11.49(DVSS2) U11.61(VSSU) U11.68(AVSS2) U12.2(A) U13.2(A) U14.2(GND) U15.2(A) U16.2(A) Y1.2(GND)
REG1: C58.2 R113.1 U10.1(VCCA)
VBUS: C62.1 C63.1 C66.1 J26.1(VBUS) TP43.1 U11.65(VBUS) U14.1(IN) U14.3(EN)
VUSB: C60.1 J27.2 R119.2 U11.66(VUSB)
DM: R114.2 U11.64(PU.1/DM)
DP: R115.2 U11.62(PU.0/DP)
LED1: D14.1(K) U11.15(P8.0)
LED2: D15.1(K) U11.16(P8.1)
LED3: D16.1(K) U11.17(P8.2)
P4_2: J25.6 U10.6(B2) U11.47(P4.2/PM_UCB1SOMI/PM_UCB1SCL)
P4_3: J25.5 U11.48(P4.3/PM_UCB1CLK/PM_UCA1STE)
PUR: J27.1 R116.1 R118.2 R119.1 U11.63(PUR)
RST: C70.1 J29.2 R123.1 S3.2 U11.76(~{RST}/NMI/SBWTDIO) U16.1(K)
SCL2: J25.8 NT3.1 U11.51(P4.4/PM_UCA1TXD/PM_UCA1SIMO) ; off-sheet uC_SCL  [also labelled uC_SCL]
SDA2: J25.9 NT4.1 U11.52(P4.5/PM_UCA1RXD/PM_UCA1SOMI) ; off-sheet uC_SDA  [also labelled uC_SDA]
SMBC1: J25.10 NT3.2 R110.2 U11.53(P4.6/PM_NONE)
SMBD1: J25.11 NT4.2 R109.2 U11.54(P4.7/PM_NONE)
TEST: J29.3 U11.71(TEST/SBWTCK) U15.1(K)
uC_HDQ: J25.7 R111.2 U11.29(P2.0/TA1.1) ; off-sheet uC_HDQ
uC_SPI_CLK: J25.2 U11.36(P2.7/UCB0STE/UCA0CLK) ; off-sheet uC_SPI_CLK
uC_SPI_CS: J25.1 U11.39(P3.2/UCB0CLK/UCA0STE) ; off-sheet uC_SPI_CS
uC_SPI_MISO_A: U10.2(A1) ; off-sheet uC_SPI_MISO_A
uC_SPI_MISO_B: J25.4 U10.7(B1) U11.41(P3.4/UCA0RXD/UCA0SOMI)
uC_SPI_MOSI: J25.3 U11.40(P3.3/UCA0TXD/UCA0SIMO) ; off-sheet uC_SPI_MOSI
NetC61_1: C61.1 U11.20(VCORE)
NetC67_1: C67.1 U11.67(V18)
NetD14_2: D14.2(A) R120.1
NetD15_2: D15.2(A) R121.1
NetD16_2: D16.2(A) R122.1
NetJ24_1: J24.1 U11.21(P1.0/TA0CLK/ACLK)
NetJ24_2: J24.2 U11.22(P1.1/TA0.0)
NetJ24_3: J24.3 U11.23(P1.2/TA0.1)
NetJ24_4: J24.4 U11.24(P1.3/TA0.2)
NetJ24_5: J24.5 U11.25(P1.4/TA0.3)
NetJ24_6: J24.6 U11.26(P1.5/TA0.4)
NetJ24_7: J24.7 U11.27(P1.6/TA1CLK/CBOUT)
NetJ26_2: J26.2(D-) R114.1 U12.1(K)
NetJ26_3: J26.3(D+) R115.1 R116.2 U13.1(K)
NetJ26_6: J26.6 J26.7 J26.8 J26.9 J26.10 J26.11 R117.2
NetJ28_1: J28.1 U11.57(P7.4/TB0.2)
NetJ28_2: J28.2 U11.58(P7.5/TB0.3)
NetJ28_3: J28.3 U11.59(P7.6/TB0.4)
NetJ28_4: J28.4 U11.60(P7.7/TB0CLK/MCLK)
NetR112_2: R112.2 TP42.1 U10.3(A2)
NetR113_2: R113.2 U10.5(DIR)
NetU11_69: U11.69(P5.2/XT2IN) Y1.1(In)
NetU11_70: U11.70(P5.3/XT2OUT) Y1.3(Out)

Not connected (* = marked no-connect by the designer): J26 4(ID)*; J29 1*; S3 MP1* MP2* MP3* MP4*; U11 1(P6.4/CB4/A4) 2(P6.5/CB5/A5) 3(P6.6/CB6/A6) 4(P6.7/CB7/A7) 5(P7.0/CB8/A12) 6(P7.1/CB9/A13) 7(P7.2/CB10/A14) 8(P7.3/CB11/A15) 9(P5.0/A8/VREF+/VEREF+)* 10(P5.1/A9/VREF-/VEREF-)* 12(P5.4/XIN)* 13(P5.5/XOUT) 28(P1.7/TA1.0)* 30(P2.1/TA1.2) 31(P2.2/TA2CLK/SMCLK) 32(P2.3/TA2.0) 33(P2.4/TA2.1) 34(P2.5/TA2.2) 35(P2.6/RTCCLK/DMAE0) 37(P3.0/UCB0SIMO/UCB0SDA)* 38(P3.1/UCB0SOMI/UCB0SCL)* 42(P3.5/TB0.5)* 43(P3.6/TB0.6)* 44(P3.7/TB0OUTH/SVMOUT)* 45(P4.0/PM_UCB1STE/PM_UCA1CLK) 46(P4.1/PM_UCB1SIMO/PM_UCB1SDA) 55(P5.6/TB0.0)* 56(P5.7/TB0.1)* 72(PJ.0/TDO) 73(PJ.1/TDI/TCLK) 74(PJ.2/TMS) 75(PJ.3/TCK) 77(P6.0/CB0/A0) 78(P6.1/CB1/A1) 79(P6.2/CB2/A2) 80(P6.3/CB3/A3); U14 4(NC)*

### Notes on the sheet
- Level Translation for digital signals from device to uC
- P7.5/TB0.3
- (near J28) P7.6/TB0.4
- P7.4/TB0.2
- (near J28) P7.7/TB0CLK/MCLK
- GND

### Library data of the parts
C58-C60 C62 C65 C66 C68 = CMP-0006228-2: CAP, CERM, 0.1 uF, 16 V, +/- 10%, X7R, 0402; Manufacturer: Wurth Elektronik; Polarized: N; Value: 0.1uF; U/M: EA; Cap_F: 100nF; Value1: Unknown; VDC_V: 16V; TaMin_C: -55°C; TaMax_C: 125°C; AEC Category: Q200; SizeArea_mm2: 0.5; SizeAreaWB_mm2: 3; SizeX_mm: 1; SizeZ_mm: 0.6
C61 C67 C69 = CMP-0006199-2: CAP, CERM, 0.47 uF, 6.3 V, +/- 10%, X5R, 0402; PartNumber: 04026D474KAT2A; Manufacturer: AVX; Polarized: N; Value: 0.47uF; U/M: EA; Cap_F: 470nF; Value1: Unknown; VDC_V: 6.3V; TaMin_C: -55°C; TaMax_C: 85°C; SizeArea_mm2: 0.5; SizeAreaWB_mm2: 3; SizeX_mm: 1; SizeZ_mm: 0.6; AEC Category: Q200; Green_Lifecycle: Active; Green_REACh: Passed
C63 C64 = CMP-0085538-1: CAP, CERM, 10 µF, 16 V,+/- 10%, X5R, 0805; Manufacturer: Samsung Electro-Mechanics; Polarized: N; Value: 10uF; U/M: EA; VDC_V: 16V; TaMin_C: -55°C; TaMax_C: 85°C; Cap_Case: 0805; SizeArea_mm2: 2.5; SizeAreaWB_mm2: 6.75; SizeX_mm: 2; SizeY_mm: 1.25; SizeZ_mm: 1.45; AEC Category: Q200
C70 = CMP-0006224-2: CAP, CERM, 2200 pF, 10 V, +/- 10%, X7R, 0402; Manufacturer: Wurth Elektronik; Polarized: N; Value: 2200pF; U/M: EA; Cap_F: 2.2nF; Value1: Unknown; VDC_V: 10V; TaMin_C: -55°C; TaMax_C: 125°C; AEC Category: Q200; SizeArea_mm2: 0.5; SizeAreaWB_mm2: 3; SizeX_mm: 1; SizeZ_mm: 0.6
D14-D16 = CMP-0002894-2: LED, Green, SMD; Manufacturer: Wurth Elektronik; Type: AlInGaP; Value2: 2V; Io_A: 20mA; Value1: W
J24 = CMP-0054584-1: Header, 2.54 mm, 7x1, Gold, TH; Manufacturer: Sullins Connector Solutions; CNHeader: TRUE; Current_A: 3A; Shrouded: N; Gender: Male; Voltage_V: 1.8kV; Row_Count: 1; Pitch_mm: 2.54; CT: FALSE; Cert_UL: Y
J25 = CMP-0054585-1: Header, 2.54 mm, 11x1, Gold, TH; Manufacturer: Sullins Connector Solutions; CNHeader: TRUE; Current_A: 3A; Shrouded: N; Gender: Male; Voltage_V: 1.8kV; Row_Count: 1; Pitch_mm: 2.54; CT: FALSE; Cert_UL: Y
J26 = CMP-0055304-1: Receptacle, Micro-USB Type B, 0.65 mm, 5x1, R/A, Bottom Mount SMT; PartNumber: 47346-1001; Manufacturer: Molex; SymbolCreator: a0411947; CompType: USB; Gender: Female; CT: TRUE; CNHeader: FALSE
J27 = CMP-0054794-2: Header, 2.54 mm, 2x1, Gold, TH; Manufacturer: Wurth Elektronik; Green_Lifecycle: Active; Green_REACh: Passed; Cert_UL: Y; Gender: Male; Pitch_mm: 2.54; Row_Count: 1; Shrouded: N
J28 = CMP-0054597-1: Header, 2.54mm, 5x1, Tin, TH; Manufacturer: Sullins Connector Solutions; CNHeader: TRUE; Current_A: 3A; Green_Lifecycle: Not Set; Shrouded: N; Gender: Male; Green_REACh: Incomplete; Voltage_V: 1.8kV; Row_Count: 1; Pitch_mm: 2.54; CT: FALSE; Cert_UL: Y
J29 = CMP-0055331-1: Header, 2.54mm, 4x1, Tin, TH; Manufacturer: Molex; Pitch_mm: 2.54; Gender: Male; Shrouded: N; Row_Count: 1; Current_A: 4A; Voltage_V: 250V; Cert_UL: Y; CNHeader: TRUE; CT: FALSE
NT3-NT5 = CMP-0078142-3: Single point connection between nets.
R109 R111 = CMP-0025701-4: RES, 10 k, 5%, 0.1 W, AEC-Q200 Grade 0, 0603; Manufacturer: Vishay-Dale; Power_W: 100mW; TempCo: 200 ppm/C; Value_Code: 10k0; Value: 10k; EIA_Code: E24; SizeX_mm: 1.6; SizeY_mm: 0.8; SizeZ_mm: 1; Value2: 0.1W; SizeArea_mm2: 1.28; AEC Qualified: Y; VDC_V: 75V; AEC Category: Q200; AEC Grade: 0
R110 = CMP-0025701-4: RES, 10 k, 5%, 0.1 W, AEC-Q200 Grade 0, 0603; Manufacturer: Vishay-Dale; Power_W: 100mW; TempCo: 200 ppm/C; Value_Code: 10k0; Value: 10k; EIA_Code: E24; SizeX_mm: 1.6; SizeY_mm: 0.8; SizeZ_mm: 1; Value2: 0.1W; SizeArea_mm2: 1.28; CompType: Resistor; AEC Qualified: Y; VDC_V: 75V; AEC Category: Q200; AEC Grade: 0
R112 R113 = CMP-0025697-4: as R56 on sheet BMS029B_FETs
R114 R115 = CMP-0026908-3: RES, 33, 5%, 0.063 W, AEC-Q200 Grade 0, 0402; PartNumber: CRCW040233R0JNED; Manufacturer: Vishay-Dale; Value: 33; Value_Code: 33R0; Power_W: 63mW; Value2: 0.063W; VDC_V: 50V; TempCo: 200 ppm/C; SizeArea_mm2: 0.5; SizeX_mm: 1; SizeZ_mm: 0.6; EIA_Code: E24; U/M: EA; AEC Category: Q200; AEC Qualified: Y; AEC Grade: 0
R116 = CMP-0026889-5: RES, 2.0 k, 5%, 0.063 W, AEC-Q200 Grade 0, 0402; PartNumber: CRCW04022K00JNED; Manufacturer: Vishay-Dale; Value: 2.0k; Res_ohm: 2k; Value_Code: 2k00; Power_W: 63mW; Value2: 0.063W; VDC_V: 50V; TempCo: 200 ppm/C; SizeArea_mm2: 0.5; SizeX_mm: 1; SizeZ_mm: 0.6; EIA_Code: E24; U/M: EA; AEC Category: Q200; AEC Qualified: Y; AEC Grade: 0
R117 R123 = CMP-0026825-5: RES, 10 k, 5%, 0.063 W, AEC-Q200 Grade 0, 0402; PartNumber: CRCW040210K0JNED; Manufacturer: Vishay-Dale; Value: 10k; Value_Code: 10k0; Power_W: 63mW; Value2: 0.063W; VDC_V: 50V; TempCo: 200 ppm/C; EIA_Code: E24; U/M: EA; AEC Category: Q200; AEC Qualified: Y; AEC Grade: 0; SizeArea_mm2: 0.5; SizeX_mm: 1; SizeZ_mm: 0.6
R118 R119 = CMP-0026859-2: RES, 1.0 M, 5%, 0.063 W, AEC-Q200 Grade 0, 0402; PartNumber: CRCW04021M00JNED; Manufacturer: Vishay-Dale; Value: 1.0Meg; Res_ohm: 1M; Value_Code: 1M00; Power_W: 63mW; Value2: 0.063W; VDC_V: 50V; TempCo: 200 ppm/C; SizeArea_mm2: 0.5; SizeX_mm: 1; SizeZ_mm: 0.6; EIA_Code: E24; U/M: EA; AEC Category: Q200; AEC Qualified: Y; AEC Grade: 0
R120-R122 = CMP-0026694-1: RES, 330, 1%, 0.1 W, AEC-Q200 Grade 0, 0402; PartNumber: ERJ-2RKF3300X; Manufacturer: Panasonic; Value: 330; Value_Code: 330R; Power_W: 100mW; Value2: 0.1W; VDC_V: 50V; TempCo: 100 ppm/C; SizeArea_mm2: 0.5; SizeX_mm: 1; SizeZ_mm: 0.6; U/M: EA; AEC Category: Q200; AEC Qualified: Y; AEC Grade: 0; Green_Lifecycle: Active; Green_REACh: Passed
S3 = CMP-0002246-2: Switch, SPST-NO,  Off-Mom, 0.05A, 12VDC, SMD; Manufacturer: C&K Components; VDC_V: 12V; PositionCount: 1; CurrentRating_mA: 50A
TP42 = CMP-0078143-2: TEST POINT.  No entry in BOM.
TP43 TP44 = CMP-0055142-1: Test Point, Compact, Red, TH; Manufacturer: Keystone; U/M: EA; CNHeader: FALSE; Green_Lifecycle: Active; Green_REACh: Passed; ContactFinish: Silver; CT: TRUE
TP45 = CMP-0003825-1: 1mm Test Point, SMT; Manufacturer: Any
U10 = CMP-0051048-2: Dual-Bit Dual Supply Transceiver with Configurable Voltage Translation and 3-State Outputs, DCT0008A, LARGE T&R; Manufacturer: Texas Instruments; Rating: Military; Input Type: CMOS/TTL; Schmitt Trigger: No; ICC @ Nom Voltage(Max)(mA): 0.004; Bits(#): 2; Logic: True; tpd @ Nom Voltage(Max)(ns): 17.7,10.3,8.3,7.2; VCC(Min)(V): 1.65; Voltage(Nom)(V): 1.8,2.5,3.3,5; Output Type: CMOS; F @ Nom Voltage(Max)(Mhz): 150; Technology Family: LVC; VCC(Max)(V): 5.5; Output Drive (IOL/IOH)(Max)(mA): 32/-32; 3-State Output: Yes; Sub-Family: Dual Supply Translator; AEC Category: Q200; AEC Qualified: N; CompType: IC; SizeAreaWB_mm2: 19; SizeArea_mm2: 11.2; SizeX_mm: 4; SizeY_mm: 2.8; SizeZ_mm: 1.3
U11 = CMP-0038965-1: 25 MHz Mixed Signal Microcontroller with 128 KB Flash, 8192 B SRAM and 63 GPIOs, -40 to 85 degC, 80-pin QFP (PN), Green (RoHS & no Sb/Br); Manufacturer: Texas Instruments; ADC: 12-bit SAR; ADC Channels: 16; Brown Out Reset: Yes; DMA: 3; Flash(KB): 128; Frequency(MHz): 25; GPIO: 63; Multiplier: 32x32; SRAM(B): 8192; SubFamily: 5 Series; Timers - 16-bit: 4; USB: 1; USCI_A (UART/LIN/IrDA/SPI): 2
U12 U13 U15 U16 = CMP-0043094-3: Single-Channel ESD in 0402 Package With 10pF Capacitance and 6V Breakdown, DPY0002A (X1SON-2); Manufacturer: Texas Instruments; Alternate PartNumber: TPD1E10B06DPYR; IEC 61000-4-2 Air-Gap(+/- kV): 30; Eco-Plan: TBD; IO Capacitance(Typ)(pF): 10; Breakdown Voltage(Min)(V): 6; AEC Category: Q200; AEC Qualified: N; CompType: IC; SizeAreaWB_mm2: 3.2; SizeArea_mm2: 0.6; SizeX_mm: 1.0; SizeZ_mm: 0.45; Rating: Catalog
U14 = CMP-0035539-1: Single Output LDO, 150 mA, Fixed 3.3 V Output, 2.7 to 10 V Input, with Low IQ, 5-pin SOT-23 (DBV), -40 to 125 degC, Green (RoHS & no Sb/Br); Manufacturer: Texas Instruments; Accuracy(%): 3; Fixed Output Options(V): 3.3; Iout(Max)(A): 0.15; Iq(Typ)(mA): 0.08; SubFamily: Single Channel LDO; Vdo(Typ)(mV): 300; Vin(Max)(V): 10; Vin(Min)(V): 2.7
Y1 = CMP-0084387-1: Resonator, 4 MHz, 39 pF, AEC-Q200 Grade 1, SMD; Manufacturer: MuRata; Frequency_Fixed: 4MHz; SizeAreaWB_mm2: 16.5; SizeArea_mm2: 9; SizeX_mm: 4.5; SizeY_mm: 2; SizeZ_mm: 1.2; TaMin_C: -40°C; TaMax_C: 125°C; AEC Category: Q200; AEC Grade: 1; AEC Qualified: Y; Load Capacitance: 39 pF

## Sheet BMS029B_Hardware.SchDoc: Hardware
size 431 x 279 mm; Date: Not shown in title block; ApprovedBy: Not shown in title block; CheckedBy: Not shown in title block; Author: Not shown in title block; CompanyName: Not shown in title block; DrawnBy: W Massoth; Engineer: Not shown in title block; Organization: Not shown in title block; Address1: Not shown in title block; Address2: Not shown in title block; Address3: Not shown in title block; Address4: Not shown in title block; DocumentNumber: 5; Revision: Use project parameter SCH_Rev; SheetNumber: 5; SheetTotal: 5; PageSetup: Record=PageOptions¦CenterHorizontal=True¦CenterVertical=True¦PrintScale=1.00¦XCorrection=1.00¦YCorrection=1.00¦PrintKind=0¦BorderSize=5000000¦LeftOffset=0¦BottomOffset=0¦Orientation=2¦PaperLength=1000¦PaperWidth=1000¦Scale=100¦PaperSource=15¦PrintQuality=600¦MediaType=1¦DitherType=10¦PaperKind=Letter¦PrintScaleMode=1
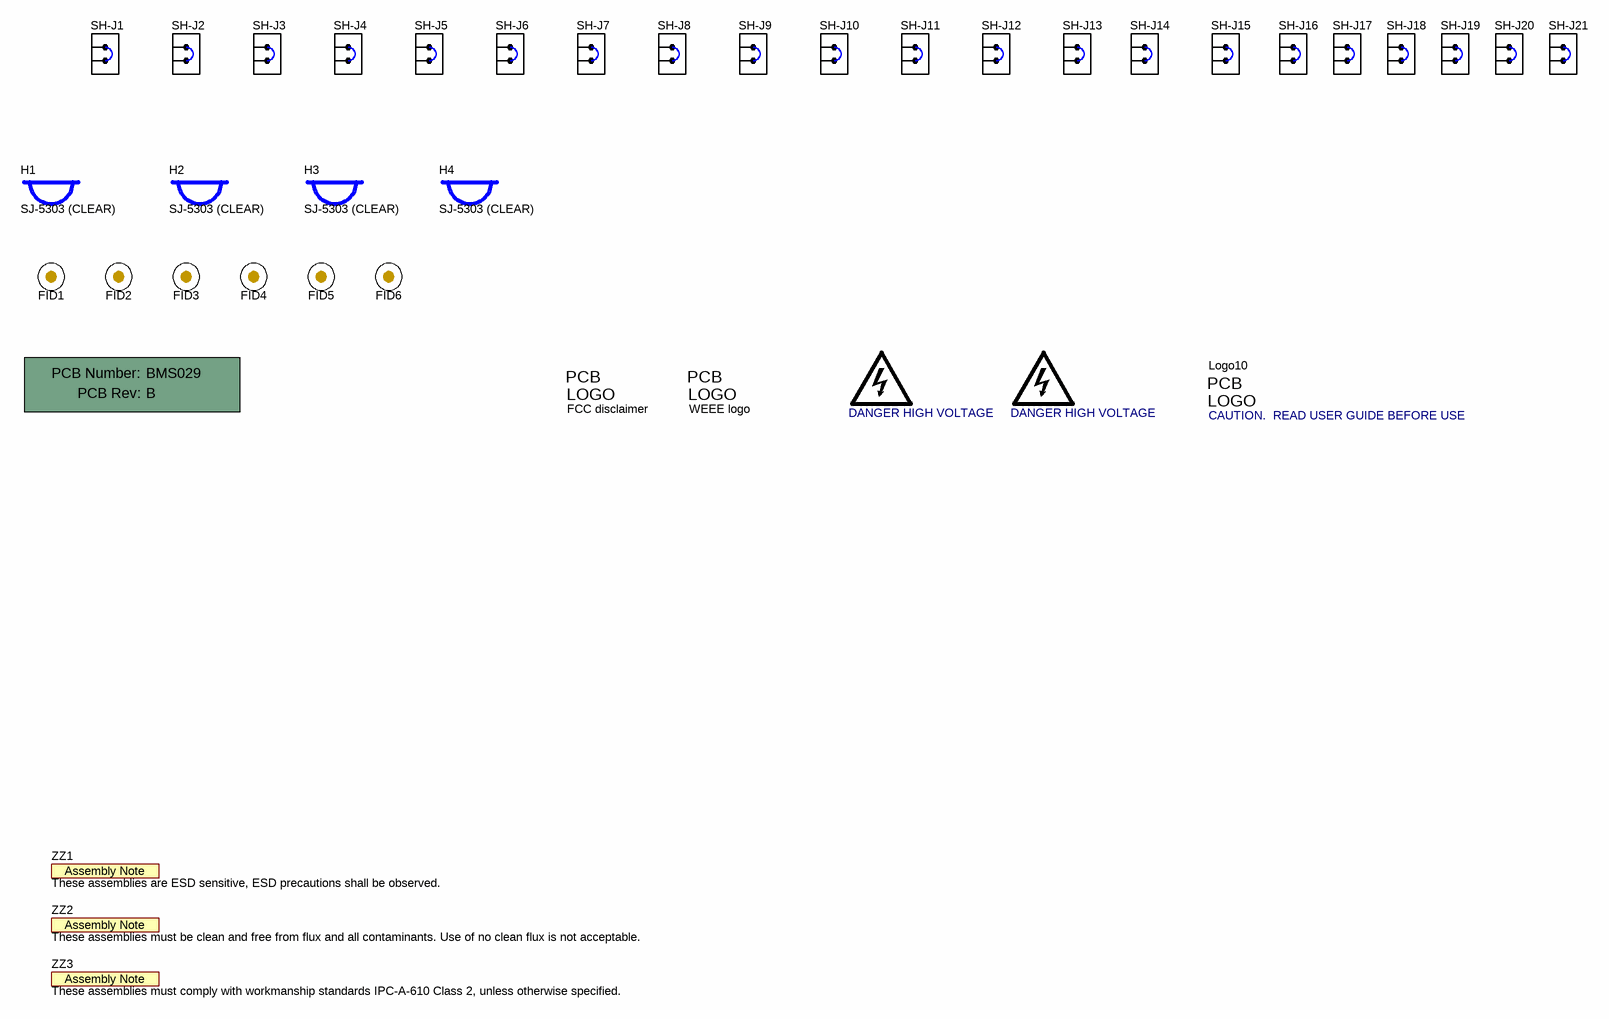
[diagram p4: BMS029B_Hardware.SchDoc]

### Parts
!PCB1  Printed Circuit Board  (value not drawn)  (mechanical)
FID1  Fiducial  [Fiducial10-20]  (value not drawn)
FID2  Fiducial  [Fiducial10-20]  (value not drawn)
FID3  Fiducial  [Fiducial10-20]  (value not drawn)
FID4  Fiducial  [Fiducial10-20]  (value not drawn)
FID5  Fiducial  [Fiducial10-20]  (value not drawn)
FID6  Fiducial  [Fiducial10-20]  (value not drawn)
H1  SJ-5303 (CLEAR)  [Bumpon_SJ5003Transparent]
H2  SJ-5303 (CLEAR)  [Bumpon_SJ5003Transparent]
H3  SJ-5303 (CLEAR)  [Bumpon_SJ5003Transparent]
H4  SJ-5303 (CLEAR)  [Bumpon_SJ5003Transparent]
LOGO4  DANGER HIGH VOLTAGE  [IEC_HighVoltage_Medium]  (no BOM)
LOGO5  DANGER HIGH VOLTAGE  [IEC_HighVoltage_Medium]  (no BOM)
Logo8  FCC disclaimer  [FCC_disclaimer]  (no BOM)
Logo9  WEEE logo  [WEEE_Minimum]  (no BOM)
Logo10  CAUTION.  READ USER GUIDE BEFORE USE  [IEC_Caution_Medium]  (no BOM)
SH-J1  SNT-100-BK-G  [SNT-100-BK-G]  (value not drawn)
SH-J2  SNT-100-BK-G  [SNT-100-BK-G]  (value not drawn)
SH-J3  SNT-100-BK-G  [SNT-100-BK-G]  (value not drawn)
SH-J4  SNT-100-BK-G  [SNT-100-BK-G]  (value not drawn)
SH-J5  SNT-100-BK-G  [SNT-100-BK-G]  (value not drawn)
SH-J6  SNT-100-BK-G  [SNT-100-BK-G]  (value not drawn)
SH-J7  SNT-100-BK-G  [SNT-100-BK-G]  (value not drawn)
SH-J8  SNT-100-BK-G  [SNT-100-BK-G]  (value not drawn)
SH-J9  SNT-100-BK-G  [SNT-100-BK-G]  (value not drawn)
SH-J10  SNT-100-BK-G  [SNT-100-BK-G]  (value not drawn)
SH-J11  SNT-100-BK-G  [SNT-100-BK-G]  (value not drawn)
SH-J12  SNT-100-BK-G  [SNT-100-BK-G]  (value not drawn)
SH-J13  SNT-100-BK-G  [SNT-100-BK-G]  (value not drawn)
SH-J14  SNT-100-BK-G  [SNT-100-BK-G]  (value not drawn)
SH-J15  SNT-100-BK-G  [SNT-100-BK-G]  (value not drawn)
SH-J16  SNT-100-BK-G  [SNT-100-BK-G]  (value not drawn)
SH-J17  SNT-100-BK-G  [SNT-100-BK-G]  (value not drawn)
SH-J18  SNT-100-BK-G  [SNT-100-BK-G]  (value not drawn)
SH-J19  SNT-100-BK-G  [SNT-100-BK-G]  (value not drawn)
SH-J20  SNT-100-BK-G  [SNT-100-BK-G]  (value not drawn)
SH-J21  SNT-100-BK-G  [SNT-100-BK-G]  (value not drawn)
ZZ1  These assemblies are ESD sensitive, ESD precautions shall be observed.  [AssemblyNote]  (no BOM)
ZZ2  These assemblies must be clean and free from flux and all contaminants. Use of no clean flux is not acceptable.  [AssemblyNote]  (no BOM)
ZZ3  These assemblies must comply with workmanship standards IPC-A-610 Class 2, unless otherwise specified.  [AssemblyNote]  (no BOM)

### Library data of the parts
!PCB1 = CMP-0003618-2: Manufacturer: Any; PartNumber: BMS029
FID1-FID6 = CMP-0077181-1: Fiducial mark.  There is nothing to buy or mount.
H1-H4 = CMP-0003620-1: Bumpon, Hemisphere, 0.44 X 0.20, Clear; Manufacturer: 3M
LOGO4 LOGO5 = CMP-0074835-1: IEC 61010-1 High Voltage Warning; SymbolCreator: a0412235
Logo8 = CMP-0074847-1: FCC_disclaimer; Library Reference: Logo
Logo9 = CMP-0074769-1
Logo10 = CMP-0074836-1: IEC 61010-1 Caution Warning; SymbolCreator: a0412235; Lib Reference: IEC_Caution
SH-J1-SH-J21 = CMP-0003623-3: Shunt, 100mil, Gold plated, Black; Alternate PartNumber: 969102-0000-DA; Manufacturer: Samtec; Alternate Manufacturer: 3M; Value: 1x2
ZZ1 = CMP-0077236-1
ZZ2 = CMP-0077237-1
ZZ3 = CMP-0077238-1

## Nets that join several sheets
PGND: BMS029B_Monitor (R28.1 R30.1), BMS029B_PinConfig (10 pins), BMS029B_FETs (8 pins), BMS029B_Interface (NT5.2)
REG1: BMS029B_Monitor (7 pins), BMS029B_PinConfig (5 pins), BMS029B_Interface (C58.2 R113.1 U10.1)
VSS: BMS029B_Monitor (25 pins), BMS029B_PinConfig (R91.1), BMS029B_FETs (13 pins)
1P: BMS029B_Monitor (J4.5 R23.1), BMS029B_PinConfig (J23.19), BMS029B_FETs (R86.1)
2P: BMS029B_Monitor (J4.4 R22.1), BMS029B_PinConfig (J23.17), BMS029B_FETs (R85.1)
3P: BMS029B_Monitor (J4.3 R21.1), BMS029B_PinConfig (J23.15), BMS029B_FETs (R84.1)
4P: BMS029B_Monitor (J4.2 R19.1), BMS029B_PinConfig (J23.13), BMS029B_FETs (7 pins)
5P: BMS029B_Monitor (J4.1 R18.1), BMS029B_PinConfig (J23.11), BMS029B_FETs (R78.1)
6P: BMS029B_Monitor (J3.5 R17.1), BMS029B_PinConfig (J23.9), BMS029B_FETs (R75.1)
7P: BMS029B_Monitor (J3.4 R16.1), BMS029B_PinConfig (J23.7), BMS029B_FETs (R72.1)
8P: BMS029B_Monitor (J3.3 R14.1), BMS029B_PinConfig (J23.5), BMS029B_FETs (7 pins)
9P: BMS029B_Monitor (J3.2 R13.1), BMS029B_PinConfig (J23.3), BMS029B_FETs (R54.1)
10P: BMS029B_Monitor (J3.1 R12.1), BMS029B_PinConfig (J23.1), BMS029B_FETs (R53.1)
11P: BMS029B_Monitor (J1.6 R11.1), BMS029B_PinConfig (J14.11), BMS029B_FETs (R49.1)
12P: BMS029B_Monitor (J1.5 R8.1), BMS029B_PinConfig (J14.9), BMS029B_FETs (7 pins)
13P: BMS029B_Monitor (J1.4 R7.1), BMS029B_PinConfig (J14.7), BMS029B_FETs (R37.1)
14P: BMS029B_Monitor (J1.3 R4.1), BMS029B_PinConfig (J14.5), BMS029B_FETs (R36.1)
15P: BMS029B_Monitor (J1.2 R3.1), BMS029B_PinConfig (J14.3), BMS029B_FETs (R34.1)
16P: BMS029B_Monitor (D1.2 J1.1 R2.1 TP1.1), BMS029B_PinConfig (J14.1), BMS029B_FETs (5 pins)
ALERT: BMS029B_Monitor (U1.25), BMS029B_PinConfig (J20.2 J21.2 TP41.1)
BAT-: BMS029B_Monitor (7 pins), BMS029B_PinConfig (R108.1)
CD: BMS029B_Monitor (D2.2), BMS029B_FETs (21 pins)
CFETOFF: BMS029B_Monitor (J5.3 U1.29), BMS029B_PinConfig (6 pins)
CHG: BMS029B_Monitor (U1.45), BMS029B_FETs (R61.1 TP30.1)
DSG: BMS029B_Monitor (U1.43), BMS029B_FETs (D9.1 D10.1 R68.1 TP35.1)
FUSE: BMS029B_Monitor (U1.38), BMS029B_FETs (R59.2)
HDQ: BMS029B_Monitor (U1.28), BMS029B_PinConfig (6 pins)
LD: BMS029B_Monitor (U1.41), BMS029B_FETs (D12.1 R76.2 TP34.1)
PACK: BMS029B_Monitor (U1.42), BMS029B_FETs (D11.1 R70.2 R73.2 TP33.1)
PCHG: BMS029B_Monitor (U1.40), BMS029B_FETs (R62.1 TP31.1)
PDSG: BMS029B_Monitor (U1.39), BMS029B_FETs (R63.1 TP32.1)
SCL: BMS029B_Monitor (U1.26), BMS029B_PinConfig (7 pins)
SCL2: BMS029B_PinConfig (J19.3), BMS029B_Interface (J25.8 NT3.1 U11.51)
SDA: BMS029B_Monitor (U1.27), BMS029B_PinConfig (7 pins)
SDA2: BMS029B_PinConfig (J16.3), BMS029B_Interface (J25.9 NT4.1 U11.52)
uC_HDQ: BMS029B_PinConfig (J13.3 J21.1), BMS029B_Interface (J25.7 R111.2 U11.29)
uC_SPI_CLK: BMS029B_PinConfig (J19.1), BMS029B_Interface (J25.2 U11.36)
uC_SPI_CS: BMS029B_PinConfig (J10.1), BMS029B_Interface (J25.1 U11.39)
uC_SPI_MISO_A: BMS029B_PinConfig (J16.1), BMS029B_Interface (U10.2)
uC_SPI_MOSI: BMS029B_PinConfig (J13.1), BMS029B_Interface (J25.3 U11.40)

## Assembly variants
001: not fitted C26 C29 C30 C34 C36 D10 D11 D12 F1 FID1 FID2 FID3 FID4 FID5 FID6 J8 J24 J25 J28 Q2 Q3 Q7 R6 R10 R15 R33 R35 R46 R55 R70 R71 TP1 TP9 TP43 TP44 TP45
